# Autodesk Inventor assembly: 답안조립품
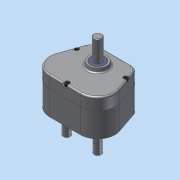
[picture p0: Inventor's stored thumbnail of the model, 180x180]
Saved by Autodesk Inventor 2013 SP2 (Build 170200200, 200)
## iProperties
Created: 2014-12
Part Number: 답안조립품
Document SubType Name: Assembly
Designer: dgall
Author: dgall
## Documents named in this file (14)
- C:\Documents and Settings\dgall\바탕 화면\441208V1029\답안조립품.iam
- C:\Documents and Settings\dgall\바탕 화면\441208V1029\본체.ipt
- C:\Documents and Settings\dgall\바탕 화면\441208V1029\오일시일-D-15.ipt
- C:\Documents and Settings\dgall\바탕 화면\441208V1029\커버.ipt
- C:\Documents and Settings\dgall\바탕 화면\441208V1029\오일시일-D-17.ipt
- C:\Documents and Settings\dgall\바탕 화면\441208V1029\베어링- 6203.ipt
- C:\Documents and Settings\dgall\바탕 화면\441208V1029\베어링- 6202.ipt
- C:\Documents and Settings\dgall\바탕 화면\441208V1029\메인축.ipt
- C:\Documents and Settings\dgall\바탕 화면\441208V1029\멈춤링.ipt
- C:\Documents and Settings\dgall\바탕 화면\441208V1029\서브축.ipt
- C:\Documents and Settings\dgall\바탕 화면\441208V1029\키5x5.ipt
- C:\Documents and Settings\dgall\바탕 화면\441208V1029\메인기어.ipt
- C:\Documents and Settings\dgall\바탕 화면\441208V1029\서브기어.ipt
- C:\Documents and Settings\dgall\바탕 화면\441208V1029\M 5 x 35.ipt
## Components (15 placed, 6 different names)
1. KS B 2804 D D - 15 30 7:1
2. KS B 2804 D D - 15 30 7:2
3. KS B 2804 D D - 17 30 8:1
4. KS B 2023 6203 - 17 x 40 x 12:1
5. KS B 2023 6203 - 17 x 40 x 12:2
6. KS B 2023 6202 - 15 x 35 x 11:1
7. KS B 2023 6202 - 15 x 35 x 11:2
8. KS B 2023 6203 - 17 x 40 x 12:3
9. KS B 2023 6203 - 17 x 40 x 12:4
10. KS B 1336 17 x 1:1
11. KS B 1336 17 x 1:2
12. KS B 1336 17 x 1:3
13. KS B 1003 - 미터 M 5 x 35:1
14. KS B 1003 - 미터 M 5 x 35:2
15. KS B 1003 - 미터 M 5 x 35:3
